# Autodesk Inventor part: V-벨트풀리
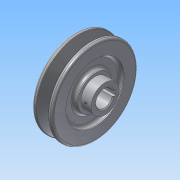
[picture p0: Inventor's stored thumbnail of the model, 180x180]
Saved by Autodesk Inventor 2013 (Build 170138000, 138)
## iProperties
Company: 한국ATC센터
Created: 2014-07
Part Number: V-벨트풀리
Document SubType Name: Modeling
Designer: KYOUNG IL JANG
Density: 2.71 g/cm^3
Material: 알루미늄 6061
Mass: 204.46 g
Surface Area: 234.122 cm^2
Volume: 75.4466 cm^3
Author: KYOUNG IL JANG
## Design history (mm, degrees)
sketch "스케치1"
  geometry: L1 (-15, 0)-(15, 0); L2 (-15, 0)-(-15, 17); L3 (-15, 17)-(-11, 17); L4 (-11, 17)-(-11, 29); L5 (-11, 29)-(-15, 29); L6 (-15, 29)-(-15, 42.5); L7 (-15, 42.5)-(-10.976, 42.5); L8 (-10.976, 42.5)-(-7.154, 30); L9 (-7.154, 30)-(-2.846, 30); L10 (-2.846, 30)-(0.976, 42.5); L11 (0.976, 42.5)-(5, 42.5); L12 (5, 42.5)-(5, 29); L13 (5, 29)-(1, 29); L14 (1, 29)-(1, 17); L15 (1, 17)-(5, 17); L16 (5, 17)-(5, 14); L17 (5, 14)-(15, 14); L18 (15, 14)-(15, 0); L19 (-9.6, 38)-(-0.4, 38); 2 further points
  constraints: 38 end point, 11 parallel, 7 collinear, 3 equal length, 3 perpendicular, 2 point on line, 1 coincident, 1 horizontal, 1 midpoint
  dimensions: "d0" = 30 distance of L1.start L1.end; "d1" = 4.5 distance between parallel lines of L7 L19; "d2" = 8 distance between parallel lines of L9 L19; "d3" = 9.2 distance of L19.start L19.end; "d4" = 34 deg angle of L10 L8; "d5" = 20 distance between parallel lines of L12 L6; "d6" = 76 diameter of L19 L1; "d7" = 4 distance of L2.end L3.end; "d8" = 34 diameter of L3 L1; "d9" = 58 diameter of L5 L1; "d10" = 28 diameter of L17 L1
revolve "회전1" sketch "스케치1" stored, may be unused: angle "d11" = 90 deg
sketch "스케치2"
  geometry: L1 (-2.5, 8.124)-(-2.5, 10.8); L2 (-2.5, 10.8)-(2.5, 10.8); L3 (2.5, 10.8)-(2.5, 8.124); A1 r 8.5 centre (0, 0) between (-2.5, 8.124) and (2.5, 8.124); 1 further point
  constraints: 6 end point, 2 parallel, 2 point on circle, 1 centre point, 1 coincident, 1 horizontal, 1 vertical
  dimensions: "d12" = 17 diameter of A1; "d13" = 5 distance of L1.end L2.end; "d14" = 19.3 dimension on A1 L2 (computed from d12)
extrude "돌출1" cut sketch "스케치2" stored distance "d15" = 10; taper "d16" = 0 deg
chamfer "모따기1" distance "d17" = 1; stored, may be unused: second distance "d18" = 2, angle "d19" = 45 deg
node "작업 평면1"
sketch "스케치3"
  geometry: L1 (5, -14)-(5, 14) reference; 3 further points
  constraints: 1 horizontal alignment, 1 midpoint
  dimensions: "d20" = 5 distance from line of L1 point (0, 0)
hole "구멍1" sketch "스케치3" at (0, 0) diameter "d21" = 3.242; stored, may be unused: countersink angle "d25" = 90 deg, drill point angle "d27" = 118 deg; dims "d22" = 6, "d23" = 4, "d24" = 2, "d26" = 8
fillet "모깎기1" dims "d28" = 3, "d29" = 2, "d30" = 0.5, "d31" = 1
node "솔리드1"
